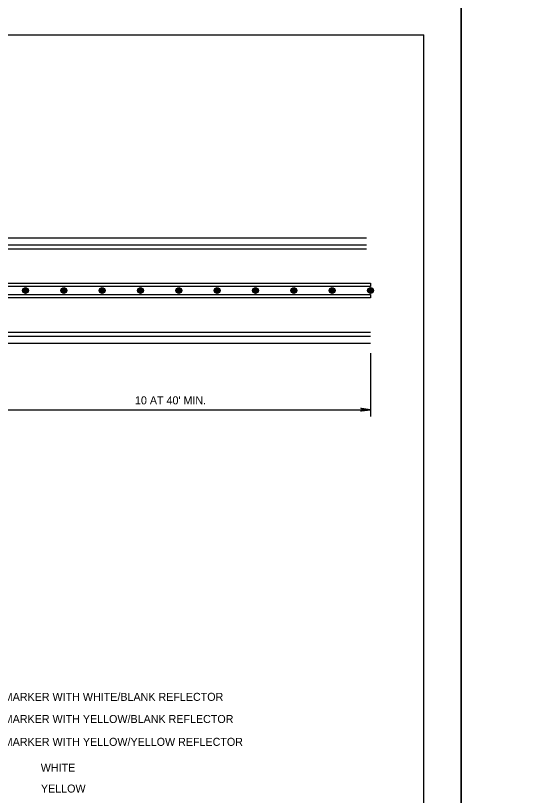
# Model space of a CAD drawing. Extents: x 639362 to 641108, y 298458 to 299646.
# Drawn here: x 640036.4 to 640225.9, y 298752.3 to 299044.4 of the extents above; entities that cross this region are included whole.
import ezdxf

# ---------------------------------------------------------------- set-up
doc = ezdxf.new("R2010")
doc.units = 0
for name, color, linetype in [('1', 7, 'Continuous'), ('2', 7, 'Continuous'), ('3', 7, 'Continuous'), ('PLT-BNDY', 7, 'Continuous')]:
    doc.layers.add(name, color=color, linetype=linetype)

# ---------------------------------------------------------------- blocks, each defined once
blk = doc.blocks.new('RARROW')
at = {"layer": '3'}
blk.add_lwpolyline([(-2.2695, 0.285), (-2.184875, 0.12075), (0, 0), (-2.2695, 0.285), (-2.38575, 0.384625), (0, 0), (-2.183125, -0.108), (-2.262875, -0.2705), (0, 0), (-2.38575, -0.379125), (-2.262875, -0.2705)], dxfattribs=at)

msp = doc.modelspace()

# ---------------------------------------------------------------- linework, layer by layer
at = {"layer": '1'}
for p in [(639403.27, 299037.19), (640189.27, 298473.19)]:
    msp.add_line(p, (640189.27, 299037.19), dxfattribs=at)
at = {"layer": '2'}
for p, q in [((640025.73, 298961.2), (640167.82, 298961.2)), ((640025.73, 298958.51), (640167.82, 298958.51)), ((640025.73, 298957.01), (640167.82, 298957.01)), ((640025.73, 298944.19), (640169.33, 298944.19)), ((640169.33, 298944.19), (640169.33, 298942.99)), ((640169.33, 298942.99), (640025.61, 298942.99)), ((640025.63, 298939.88), (640169.33, 298939.88)), ((640169.33, 298938.68), (640025.73, 298938.68)), ((640169.33, 298939.88), (640169.33, 298938.68)), ((640025.73, 298925.85), (640169.33, 298925.85)), ((640025.73, 298924.35), (640169.33, 298924.35)), ((640025.73, 298921.72), (640169.33, 298921.72)), ((640169.35, 298917.97), (640169.35, 298894.23)), ((640025.73, 298896.78), (640169.33, 298896.78))]:
    msp.add_line(p, q, dxfattribs=at)
for centre, radius in [((640040.09, 298941.43), 1.1), ((640040.09, 298941.43), 1.02), ((640040.09, 298941.43), 0.946), ((640040.09, 298941.43), 0.868), ((640040.09, 298941.43), 0.789), ((640040.09, 298941.43), 0.711), ((640040.09, 298941.43), 0.633), ((640040.09, 298941.43), 0.554), ((640040.09, 298941.43), 0.476), ((640040.09, 298941.43), 0.398), ((640040.09, 298941.43), 0.32), ((640040.09, 298941.43), 0.241), ((640040.09, 298941.43), 0.163), ((640040.09, 298941.43), 0.0846), ((640054.45, 298941.43), 1.1), ((640054.45, 298941.43), 1.02), ((640054.45, 298941.43), 0.946), ((640054.45, 298941.43), 0.868), ((640054.45, 298941.43), 0.789), ((640054.45, 298941.43), 0.711), ((640054.45, 298941.43), 0.633), ((640054.45, 298941.43), 0.554), ((640054.45, 298941.43), 0.476), ((640054.45, 298941.43), 0.398), ((640054.45, 298941.43), 0.32), ((640054.45, 298941.43), 0.241), ((640054.45, 298941.43), 0.163), ((640054.45, 298941.43), 0.0846), ((640068.81, 298941.43), 1.1), ((640068.81, 298941.43), 1.02), ((640068.81, 298941.43), 0.946), ((640068.81, 298941.43), 0.868), ((640068.81, 298941.43), 0.789), ((640068.81, 298941.43), 0.711), ((640068.81, 298941.43), 0.633), ((640068.81, 298941.43), 0.554), ((640068.81, 298941.43), 0.476), ((640068.81, 298941.43), 0.398), ((640068.81, 298941.43), 0.32), ((640068.81, 298941.43), 0.241), ((640068.81, 298941.43), 0.163), ((640068.81, 298941.43), 0.0846), ((640083.17, 298941.43), 1.1), ((640083.17, 298941.43), 1.02), ((640083.17, 298941.43), 0.946), ((640083.17, 298941.43), 0.868), ((640083.17, 298941.43), 0.789), ((640083.17, 298941.43), 0.711), ((640083.17, 298941.43), 0.633), ((640083.17, 298941.43), 0.554), ((640083.17, 298941.43), 0.476), ((640083.17, 298941.43), 0.398), ((640083.17, 298941.43), 0.32), ((640083.17, 298941.43), 0.241), ((640083.17, 298941.43), 0.163), ((640083.17, 298941.43), 0.0846), ((640097.53, 298941.43), 1.1), ((640097.53, 298941.43), 1.02), ((640097.53, 298941.43), 0.946), ((640097.53, 298941.43), 0.868), ((640097.53, 298941.43), 0.789), ((640097.53, 298941.43), 0.711), ((640097.53, 298941.43), 0.633), ((640097.53, 298941.43), 0.554), ((640097.53, 298941.43), 0.476), ((640097.53, 298941.43), 0.398), ((640097.53, 298941.43), 0.32), ((640097.53, 298941.43), 0.241), ((640097.53, 298941.43), 0.163), ((640097.53, 298941.43), 0.0846), ((640111.89, 298941.43), 1.1), ((640111.89, 298941.43), 1.02), ((640111.89, 298941.43), 0.946), ((640111.89, 298941.43), 0.868), ((640111.89, 298941.43), 0.789), ((640111.89, 298941.43), 0.711), ((640111.89, 298941.43), 0.633), ((640111.89, 298941.43), 0.554), ((640111.89, 298941.43), 0.476), ((640111.89, 298941.43), 0.398), ((640111.89, 298941.43), 0.32), ((640111.89, 298941.43), 0.241), ((640111.89, 298941.43), 0.163), ((640111.89, 298941.43), 0.0846), ((640126.25, 298941.43), 1.1), ((640126.25, 298941.43), 1.02), ((640126.25, 298941.43), 0.946), ((640126.25, 298941.43), 0.868), ((640126.25, 298941.43), 0.789), ((640126.25, 298941.43), 0.711), ((640126.25, 298941.43), 0.633), ((640126.25, 298941.43), 0.554), ((640126.25, 298941.43), 0.476), ((640126.25, 298941.43), 0.398), ((640126.25, 298941.43), 0.32), ((640126.25, 298941.43), 0.241), ((640126.25, 298941.43), 0.163), ((640126.25, 298941.43), 0.0846), ((640140.61, 298941.43), 1.1), ((640140.61, 298941.43), 1.02), ((640140.61, 298941.43), 0.946), ((640140.61, 298941.43), 0.868), ((640140.61, 298941.43), 0.789), ((640140.61, 298941.43), 0.711), ((640140.61, 298941.43), 0.633), ((640140.61, 298941.43), 0.554), ((640140.61, 298941.43), 0.476), ((640140.61, 298941.43), 0.398), ((640140.61, 298941.43), 0.32), ((640140.61, 298941.43), 0.241), ((640140.61, 298941.43), 0.163), ((640140.61, 298941.43), 0.0846), ((640154.97, 298941.43), 1.1), ((640154.97, 298941.43), 1.02), ((640154.97, 298941.43), 0.946), ((640154.97, 298941.43), 0.868), ((640154.97, 298941.43), 0.789), ((640154.97, 298941.43), 0.711), ((640154.97, 298941.43), 0.633), ((640154.97, 298941.43), 0.554), ((640154.97, 298941.43), 0.476), ((640154.97, 298941.43), 0.398), ((640154.97, 298941.43), 0.32), ((640154.97, 298941.43), 0.241), ((640154.97, 298941.43), 0.163), ((640154.97, 298941.43), 0.0846), ((640169.35, 298941.43), 1.1), ((640169.35, 298941.43), 1.02), ((640169.35, 298941.43), 0.946), ((640169.35, 298941.43), 0.868), ((640169.35, 298941.43), 0.789), ((640169.35, 298941.43), 0.711), ((640169.35, 298941.43), 0.633), ((640169.35, 298941.43), 0.554), ((640169.35, 298941.43), 0.476), ((640169.35, 298941.43), 0.398), ((640169.35, 298941.43), 0.32), ((640169.35, 298941.43), 0.241), ((640169.35, 298941.43), 0.163), ((640169.35, 298941.43), 0.0846)]:
    msp.add_circle(centre, radius, dxfattribs=at)
at = {"layer": 'PLT-BNDY'}
for points in [[(639362.31, 299051.63), (640203.31, 299051.63), (640203.31, 298457.63), (639362.31, 298457.63)], [(640203.31, 299051.63), (641044.31, 299051.63), (641044.31, 298457.63), (640203.31, 298457.63)]]:
    msp.add_lwpolyline(points, close=True, dxfattribs=at)

# ---------------------------------------------------------------- block references
at = {"layer": '2', "xscale": 1.5089217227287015, "yscale": 1.5711553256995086}
msp.add_blockref('RARROW', (640169.33, 298896.78), dxfattribs=at)

# ---------------------------------------------------------------- texts
at = {"layer": '2'}
for s, p in [("10 AT 40' MIN.", (640081.11, 298898.79)), ('TWO-WAY MARKER WITH WHITE/BLANK REFLECTOR', (640011, 298787.73)), ('TWO-WAY MARKER WITH YELLOW/YELLOW REFLECTOR', (640011, 298770.88)), ('WHITE', (640045.81, 298761.19)), ('YELLOW', (640045.88, 298753.38))]:
    msp.add_text(s, height=3, dxfattribs=at).set_placement(p)
msp.add_text('TWO-WAY MARKER WITH YELLOW/BLANK REFLECTOR', height=3, rotation=360, dxfattribs=at).set_placement((640011, 298779.44))

doc.saveas('drawing.dxf')
